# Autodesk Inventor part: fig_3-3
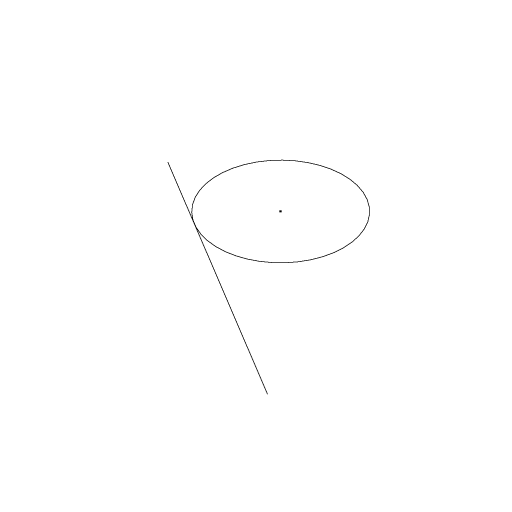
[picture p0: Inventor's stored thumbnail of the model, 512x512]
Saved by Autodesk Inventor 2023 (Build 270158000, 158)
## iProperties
Created: 2009-11
Part Number: fig_3-3
Document SubType Name: Modeling
Designer: Sham
Density: 1 g/cm^3
Material: Generic
Appearance: Default
Author: Sham
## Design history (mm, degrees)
sketch "Sketch1"
  geometry: L1 (-21, -10.296)-(20, -35); C1 r 10.296 at (-4.831, -8.018)
  constraints: 2 end point, 1 centre point, 1 tangent, 1 other
